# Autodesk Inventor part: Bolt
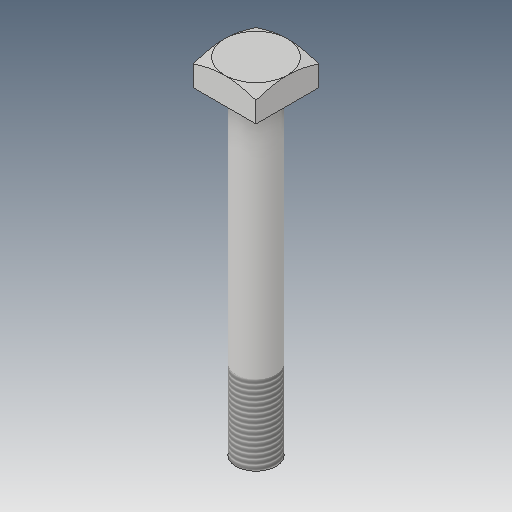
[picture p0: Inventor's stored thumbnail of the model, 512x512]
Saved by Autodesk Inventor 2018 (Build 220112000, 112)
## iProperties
Created: 2016-05
Part Number: Bolt
Material: Generic
Document SubType Name: Modeling
Designer: CADCIM
Density: 1 g/cm^3
Appearance: Default
Author: CADCIM
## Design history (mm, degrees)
sketch "Sketch1"
  geometry: L1 (9.5, 9.5)-(-9.5, 9.5); L2 (-9.5, 9.5)-(-9.5, -9.5); L3 (-9.5, -9.5)-(9.5, -9.5); L4 (9.5, -9.5)-(9.5, 9.5); L5 (0, 0)-(0, 14.108); L6 (0, 0)-(-17.802, 0)
  constraints: 12 end point, 2 horizontal, 2 parallel, 2 perpendicular, 1 vertical, 2 other
  dimensions: "d0" = 19 distance of L3.end L1.start
extrude "Extrusion1" new body sketch "Sketch1" distance "d1" = 8; taper "d2" = 0 deg
sketch "Sketch3"
  geometry: L1 (9.5, 9.5)-(-9.5, 9.5) reference; C1 r 9.5 at (0, 0); 1 further point
  constraints: 1 centre point, 1 coincident, 1 tangent
extrude "Extrusion3" sketch "Sketch3" distance "d6" = 96; taper "d7" = 65 deg
sketch "Sketch4"
  geometry: C1 r 6 at (0, 0); 1 further point
  constraints: 1 centre point, 1 coincident
  dimensions: "d10" = 12 diameter of C1
extrude "Extrusion4" join sketch "Sketch4" distance "d11" = 96; taper "d12" = 0 deg
thread "Thread2" dims "d13" = 24, "d14" = 0
body "Solid1"
